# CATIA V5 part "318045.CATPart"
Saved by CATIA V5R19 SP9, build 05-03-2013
Part number: 318045
Source: Unknown
Bounding box of the stored display mesh (mm): x -4.4 to 267.6, y 93.501 to 140.001, z 435 to 559
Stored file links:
  D:\16-SIL\kale oto\R19_V2\318045.CATPart
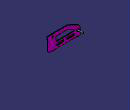
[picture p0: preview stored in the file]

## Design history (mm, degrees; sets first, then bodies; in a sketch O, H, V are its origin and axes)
Set1
  Line1: stored without definition
Body1 "120\\22\\MANIFOLD_SOLID_BREP #39330" (main body)
  Solid1: solid without history
Body2 "120\\106\\42\\MANIFOLD_SOLID_BREP #44818"
  Solid2: solid without history
Body3 "241\\220\\MANIFOLD_SOLID_BREP #154205"
  Solid3: solid without history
